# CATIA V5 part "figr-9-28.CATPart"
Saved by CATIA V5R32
Part number: Part1
Bounding box of the stored display mesh (mm): x -75 to 75, y -50 to 50, z 0 to 40
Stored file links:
  D:\PROJECTS\Project 2022\CATIA V5 6R 2022\Resources\Part Files\c09_catia_v5_6r2022_prt\c09_catia_v5_6r2022_prt\figr-9-28.CATPart
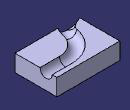
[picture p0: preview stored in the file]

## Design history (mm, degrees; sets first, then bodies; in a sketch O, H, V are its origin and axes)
Body1 (main body)
  Sketch1 on xy-plane, origin (0, 0, 0), H (1, 0, 0), V (0, 1, 0)
    line L1 (-75, 50) -> (75, 50)
    line L2 (75, 50) -> (75, -50)
    line L3 (75, -50) -> (-75, -50)
    line L4 (-75, -50) -> (-75, 50)
    axis line L5 (75, -50) -> (-75, 50)
    length L2 = 100
    length L3 = 150
    horizontal: L1 H, L3 H
    vertical: L2 V, L4 V
    midpoint: O L5
  Pad1: profile Sketch1, direction (0, 0, 1), length 40
  Sketch2 on face of Pad1, origin (75, 0, 0), H (0, 1, 0), V (0, 0, 1)
    arc A1 centre (24.1478, 40) radius 14.6047 from (9.543, 40) to (38.7525, 40) ccw
    point P1 (24.1478, 40)
    reference projected point E1 (24.1478, 40) from vertex of Sketch3
    line L1 (9.543, 40) -> (38.7525, 40)
    coincidence: P1 E1
    horizontal: L1 H
  Sketch3 on face of Pad1, origin (0, 0, 40), H (1, 0, 0), V (0, 1, 0)
    point P1 (75, 24.1478)
    line L1 (75, 24.1478) -> (28.6577, 24.1478)
    arc A1 centre (28.6577, -39.2062) radius 63.354 from (28.6577, 24.1478) to (-33.8383, -28.8149) ccw
    arc A2 centre (-62.192, -24.1005) radius 28.7429 from (-33.8383, -28.8149) to (-49.7271, -50) cw
    point P6 (-49.7271, -50)
    reference projected line E1 (75, -50) -> (75, 50) from edge [face of Pad1 | face of Pad1]
    reference projected line E2 (-75, -50) -> (75, -50) from edge [face of Pad1 | face of Pad1]
    horizontal: L1 H
    tangency: A1 L1, A2 A1
    coincidence: P1 E1, P6 E2
  Slot1: profile Sketch2, centre curve Sketch3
